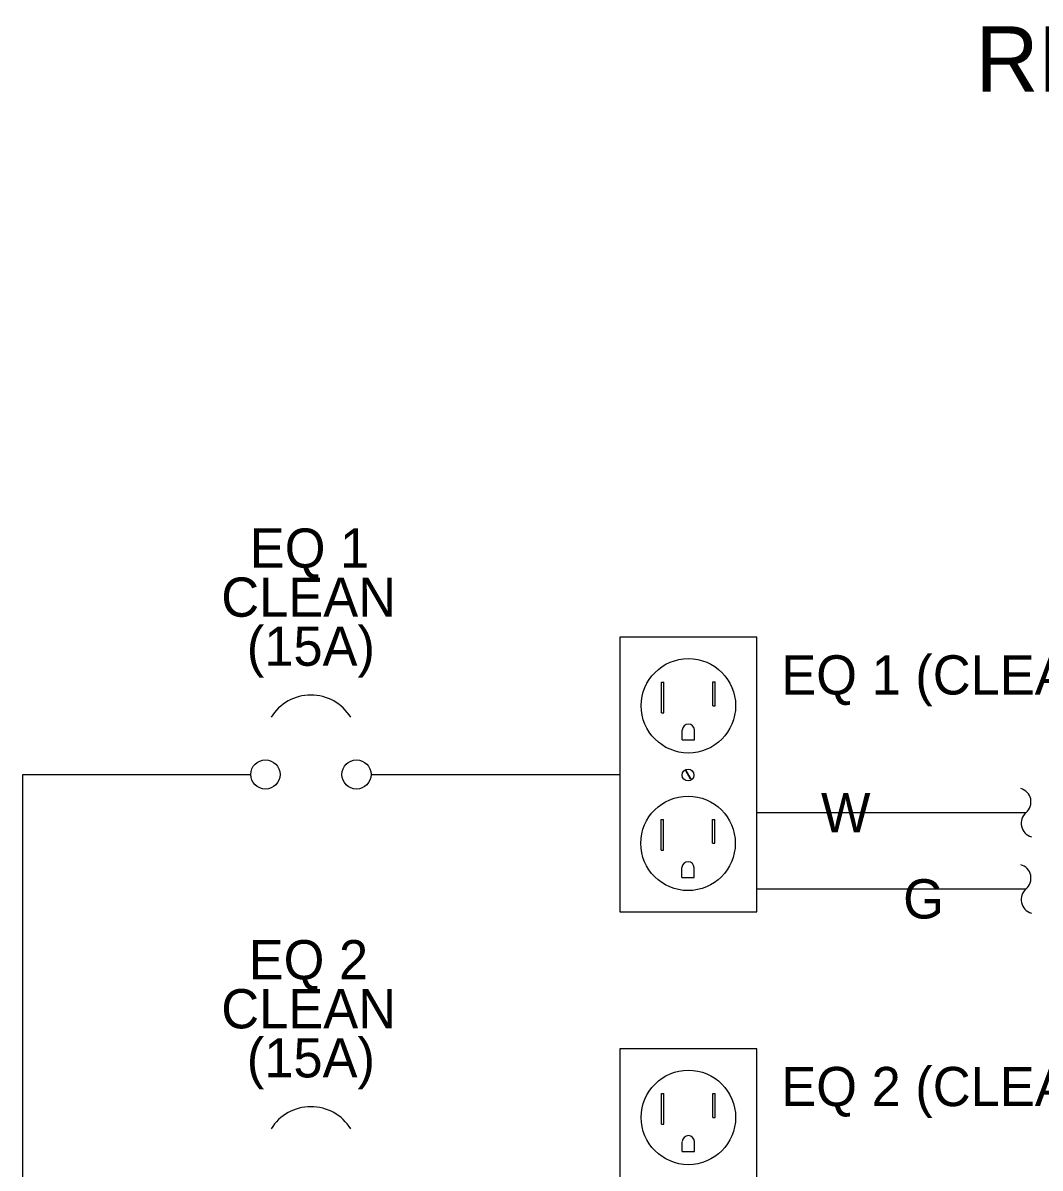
# Model space of a CAD drawing. Extents: x 99862 to 103680, y 99470 to 102076.
# Drawn here: x 100849.3 to 101160.6, y 100672.6 to 101022.9 of the extents above; entities that cross this region are included whole.
import ezdxf

# ---------------------------------------------------------------- set-up
doc = ezdxf.new("R2010")
doc.units = 0
for name, color, linetype in [('Level 11', 7, 'Continuous'), ('Level 20', 7, 'Continuous'), ('Level 26', 7, 'Continuous'), ('Level 40', 7, 'Continuous')]:
    doc.layers.add(name, color=color, linetype=linetype)

msp = doc.modelspace()

# ---------------------------------------------------------------- linework, layer by layer
at = {"layer": 'Level 11'}
for p, q in [((101044.77, 100811.87), (101044.77, 100821.26)), ((101044.77, 100821.26), (101045.47, 100821.26)), ((101045.47, 100811.87), (101045.47, 100821.26)), ((101060.41, 100814), (101060.41, 100821.28)), ((101060.41, 100821.28), (101061.15, 100821.28)), ((101061.15, 100814), (101061.15, 100821.28)), ((101060.41, 100814), (101061.15, 100814)), ((101044.77, 100811.87), (101045.47, 100811.87)), ((101051.09, 100803.53), (101051.09, 100806.56)), ((101054.82, 100803.53), (101054.82, 100806.58)), ((101051.09, 100803.53), (101054.82, 100803.53)), ((101044.66, 100769.81), (101044.66, 100779.18)), ((101044.66, 100779.18), (101045.4, 100779.18)), ((101045.4, 100769.81), (101045.4, 100779.18)), ((101060.34, 100771.92), (101060.34, 100779.24)), ((101060.34, 100779.24), (101061.06, 100779.24)), ((101061.06, 100771.92), (101061.06, 100779.24)), ((101060.34, 100771.92), (101061.06, 100771.92)), ((101044.66, 100769.81), (101045.4, 100769.81)), ((101051, 100761.47), (101051, 100764.52)), ((101054.72, 100761.47), (101054.72, 100764.39)), ((101051, 100761.47), (101054.72, 100761.47)), ((101044.77, 100685.96), (101044.77, 100695.35)), ((101044.77, 100695.35), (101045.47, 100695.35)), ((101045.47, 100685.96), (101045.47, 100695.35)), ((101060.41, 100688.09), (101060.41, 100695.37)), ((101060.41, 100695.37), (101061.15, 100695.37)), ((101061.15, 100688.09), (101061.15, 100695.37)), ((101060.41, 100688.09), (101061.15, 100688.09)), ((101044.77, 100685.96), (101045.47, 100685.96)), ((101051.09, 100677.62), (101051.09, 100680.65)), ((101054.82, 100677.62), (101054.82, 100680.67)), ((101051.09, 100677.62), (101054.82, 100677.62))]:
    msp.add_line(p, q, dxfattribs=at)
for centre in [(101052.98, 100813.98), (101052.88, 100771.91), (101052.98, 100688.07)]:
    msp.add_circle(centre, 14.45, dxfattribs=at)
for centre, start, end in [((101052.97, 100806.55), 1.1491, 179.3526), ((101052.86, 100764.41), 359.7062, 176.4581), ((101052.97, 100680.64), 1.1491, 179.3526)]:
    msp.add_arc(centre, 1.86, start, end, dxfattribs=at)
at = {"layer": 'Level 26'}
for p, q in [((100849.3, 100792.97), (100919.06, 100792.97)), ((100849.3, 100596.23), (100849.3, 100792.97)), ((100955.87, 100792.97), (101031.99, 100792.97)), ((101073.96, 100781.31), (101156.33, 100781.31)), ((101073.96, 100757.98), (101156.33, 100757.98))]:
    msp.add_line(p, q, dxfattribs=at)
for centre in [(100923.53, 100792.97), (100951.4, 100792.97)]:
    msp.add_circle(centre, 4.47, dxfattribs=at)
for centre, radius, start, end in [((100937.46, 100802.91), 14.35, 31.8159, 148.1841), ((101153.56, 100784.57), 4.28, 310.3213, 74.2832), ((101159.1, 100778.04), 4.28, 130.3213, 254.2832), ((101153.56, 100761.25), 4.28, 310.3213, 74.2832), ((101159.1, 100754.71), 4.28, 130.3213, 254.2832), ((100937.46, 100677), 14.35, 31.8159, 148.1841)]:
    msp.add_arc(centre, radius, start, end, dxfattribs=at)
at = {"layer": 'Level 40'}
for p, q in [((101053.62, 100791.53), (101052.15, 100794.07)), ((101053.82, 100791.56), (101052.29, 100794.23))]:
    msp.add_line(p, q, dxfattribs=at)
for points in [[(101031.99, 100834.93), (101031.99, 100751.01), (101073.96, 100751.01), (101073.96, 100834.93)], [(101031.99, 100709.02), (101031.99, 100625.1), (101073.96, 100625.1), (101073.96, 100709.02)]]:
    msp.add_lwpolyline(points, close=True, dxfattribs=at)
msp.add_circle((101052.88, 100792.8), 1.81, dxfattribs=at)

# ---------------------------------------------------------------- texts
at = {"layer": 'Level 20'}
for s, height, p in [('REAR VIEW (INTERIOR - FOLD DOWN PANEL)', 20, (101140.84, 101001.8)), ('EQ 1', 12, (100918.73, 100856.22)), ('CLEAN', 12, (100910.01, 100841.22)), ('(15A)', 12, (100917.82, 100826.22)), ('EQ 1 (CLEAN)', 12, (101081.4, 100817.43)), ('W', 12.01, (101093.55, 100775.3)), ('G', 12.01, (101118.7, 100748.91)), ('EQ 2', 12, (100918.39, 100730.31)), ('CLEAN', 12, (100910.01, 100715.31)), ('(15A)', 12, (100917.82, 100700.31)), ('EQ 2 (CLEAN)', 12, (101081.4, 100691.52))]:
    msp.add_text(s, height=height, dxfattribs=at).set_placement(p)

doc.saveas('drawing.dxf')
